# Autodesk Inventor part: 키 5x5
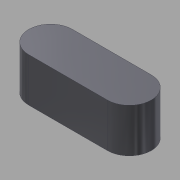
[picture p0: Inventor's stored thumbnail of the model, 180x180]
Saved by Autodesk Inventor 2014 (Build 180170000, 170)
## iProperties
Created: 2014-10
Part Number: 키 5x5
Document SubType Name: Modeling
Designer: KYOUNG IL JANG
Density: 7.86 g/cm^3
Mass: 2.54015 g
Surface Area: 2.9781 cm^2
Volume: 0.323175 cm^3
Material: 강철, 연강
Appearance: 강철 - 광택
Author: SeoGD™ [www.esajin.kr]
Revision Number: 1
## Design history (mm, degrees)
sketch "스케치1"
  geometry: L1 (-4.5, -2.5)-(4.5, -2.5); L2 (4.5, 2.5)-(-4.5, 2.5); A1 r 2.5 centre (4.5, 0) between (4.5, -2.5) and (4.5, 2.5); A2 r 2.5 centre (-4.5, 0) between (-4.5, 2.5) and (-4.5, -2.5); 2 further points
  constraints: 4 end point, 4 point on circle, 4 tangent, 2 centre point, 1 horizontal, 1 horizontal alignment, 1 midpoint, 1 parallel, 1 vertical alignment
  dimensions: "d0" = 5 distance between parallel lines of L1 L2; "d1" = 14 dimension on A1 A2
extrude "돌출1" new body sketch "스케치1" stored distance "d2" = 5; taper "d3" = 0 deg
node "솔리드1"
